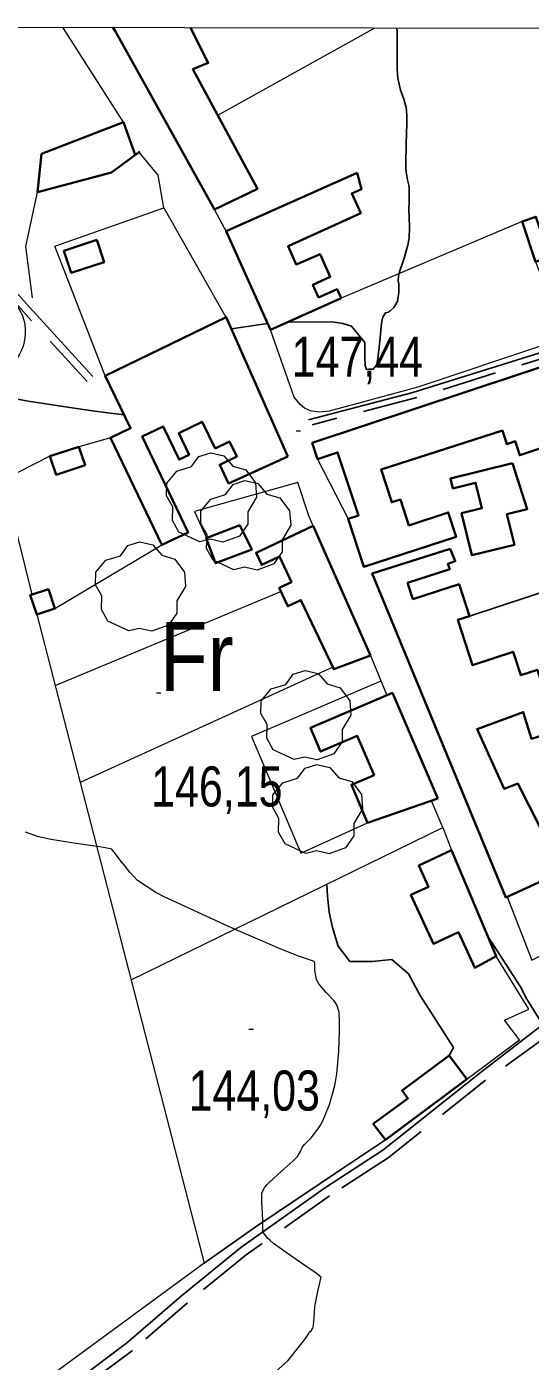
# Model space of a CAD drawing. Extents: x 483855 to 488461, y 4388206 to 4391419.
# Drawn here: x 484185.8 to 484295.6, y 4390781.6 to 4391072.6 of the extents above; entities that cross this region are included whole.
import ezdxf
from ezdxf.enums import TextEntityAlignment as Align

# ---------------------------------------------------------------- set-up
doc = ezdxf.new("R2010")
doc.units = 0
doc.header["$LTSCALE"] = 4
doc.linetypes.add('LONG_DASHED', pattern=[7.5, 6, -1.5])
doc.linetypes.add('MEDIUM_DASHED', pattern=[4.5, 3, -1.5])
for name, color, linetype, lineweight in [('1', 7, 'Continuous', 13), ('25', 7, 'LONG_DASHED', 25), ('29', 7, 'Continuous', 13), ('36', 7, 'Continuous', 25), ('38', 7, 'Continuous', 25), ('47', 7, 'Continuous', 35), ('51', 7, 'Continuous', 13), ('7', 7, 'Continuous', 13), ('8', 7, 'Continuous', 25), ('9', 7, 'Continuous', 13)]:
    doc.layers.add(name, color=color, linetype=linetype, lineweight=lineweight)
doc.layers.add('31', color=7, linetype='Continuous')

msp = doc.modelspace()

# ---------------------------------------------------------------- linework, layer by layer
at = {"layer": '1'}
msp.add_lwpolyline([(484115.5, 4391072.6), (487689.7, 4391065.7), (487685.8, 4388753.5), (484110.5, 4388760.3)], close=True, dxfattribs=at)
at = {"layer": '25'}
msp.add_line((484282.36, 4390944.05), (484413.92, 4390987.45), dxfattribs=at)
for points in [[(484251.23, 4390885.64), (484251.39, 4390883), (484251.77, 4390879.52), (484252.51, 4390876.18), (484253.71, 4390872.09), (484256.25, 4390868.8), (484261.13, 4390868.8), (484265.42, 4390869.2), (484269.07, 4390866.07), (484271.58, 4390861.38), (484278.9, 4390850.03), (484277.96, 4390848.27)], [(484224.54, 4390803), (484235.61, 4390810.89), (484254.44, 4390823.52), (484264.05, 4390829.93)]]:
    msp.add_lwpolyline(points, dxfattribs=at)
at = {"layer": '29'}
for points in [[(484223.56, 4390960.27), (484219.02, 4390962.39), (484217.61, 4390964.93), (484217.71, 4390967.91), (484216.34, 4390970.32), (484216.38, 4390973.07), (484218.54, 4390975.67), (484221.73, 4390976.67), (484223.38, 4390978.86), (484225.95, 4390979.69), (484228.81, 4390979.04), (484230.76, 4390976.77), (484233.57, 4390975.95), (484235.7, 4390973.1), (484235.94, 4390969.97), (484234.06, 4390966.82), (484234.06, 4390964.14), (484232.24, 4390961.53), (484228.62, 4390960.19), (484225.85, 4390960.82)], [(484231, 4390954.18), (484226.46, 4390956.3), (484225.05, 4390958.84), (484225.15, 4390961.82), (484223.78, 4390964.23), (484223.82, 4390966.98), (484225.98, 4390969.58), (484229.17, 4390970.58), (484230.82, 4390972.77), (484233.39, 4390973.6), (484236.25, 4390972.95), (484238.2, 4390970.68), (484241.01, 4390969.86), (484243.14, 4390967.01), (484243.38, 4390963.88), (484241.5, 4390960.73), (484241.5, 4390958.05), (484239.68, 4390955.44), (484236.06, 4390954.1), (484233.29, 4390954.73)], [(484208.08, 4390940.84), (484203.54, 4390942.96), (484202.13, 4390945.5), (484202.23, 4390948.48), (484200.86, 4390950.89), (484200.9, 4390953.64), (484203.06, 4390956.24), (484206.25, 4390957.24), (484207.9, 4390959.43), (484210.47, 4390960.26), (484213.33, 4390959.61), (484215.28, 4390957.34), (484218.09, 4390956.52), (484220.22, 4390953.67), (484220.46, 4390950.54), (484218.58, 4390947.39), (484218.58, 4390944.71), (484216.76, 4390942.1), (484213.14, 4390940.76), (484210.37, 4390941.39)], [(484244.12, 4390912.79), (484239.58, 4390914.91), (484238.17, 4390917.45), (484238.27, 4390920.43), (484236.9, 4390922.84), (484236.94, 4390925.59), (484239.1, 4390928.19), (484242.29, 4390929.19), (484243.94, 4390931.38), (484246.51, 4390932.21), (484249.37, 4390931.56), (484251.32, 4390929.29), (484254.13, 4390928.47), (484256.26, 4390925.62), (484256.5, 4390922.49), (484254.62, 4390919.34), (484254.62, 4390916.66), (484252.8, 4390914.05), (484249.18, 4390912.71), (484246.41, 4390913.34)], [(484246.68, 4390892.33), (484242.14, 4390894.45), (484240.73, 4390896.99), (484240.83, 4390899.97), (484239.46, 4390902.38), (484239.5, 4390905.13), (484241.66, 4390907.73), (484244.85, 4390908.73), (484246.5, 4390910.92), (484249.07, 4390911.75), (484251.93, 4390911.1), (484253.88, 4390908.83), (484256.69, 4390908.01), (484258.82, 4390905.16), (484259.06, 4390902.03), (484257.18, 4390898.88), (484257.18, 4390896.2), (484255.36, 4390893.59), (484251.74, 4390892.25), (484248.97, 4390892.88)]]:
    msp.add_lwpolyline(points, close=True, dxfattribs=at)
at = {"layer": '36'}
msp.add_lwpolyline([(484286.4, 4390874.18), (484293.5, 4390863.28), (484294.88, 4390860.55), (484297.89, 4390855.67), (484301.36, 4390851.1), (484304.67, 4390847.22), (484307.34, 4390843.83)], dxfattribs=at)
at = {"layer": '38'}
for points in [[(484446.6, 4391071.03), (484420.26, 4391057.4), (484410.47, 4391050.18), (484405.1, 4391046.04), (484399.1, 4391040.81), (484389.82, 4391033.18), (484375.53, 4391027.31), (484343.45, 4391017.59), (484326.91, 4391010.64), (484304.24, 4391003.47), (484269.98, 4390992.8), (484247.23, 4390986.88)], [(484200.26, 4390996.32), (484186.42, 4391011.45), (484181.12, 4391017.39), (484178.55, 4391018.61), (484169.32, 4391017.61), (484165.88, 4391015.98), (484162.83, 4391013.24), (484160.39, 4391010.8), (484157.14, 4391007.67), (484151.89, 4391001.63), (484147.35, 4390985.86), (484131.5, 4390937.5), (484130.32, 4390935.61), (484122.52, 4390930.52), (484115.19, 4390927.03)], [(484298.38, 4390855.03), (484284.66, 4390844.48), (484263.45, 4390827.61), (484250.72, 4390819.35), (484232.48, 4390806.42), (484219.57, 4390795.92), (484207.6, 4390785.54), (484197.08, 4390777.65), (484194.16, 4390775.6), (484191.43, 4390772.82), (484188.02, 4390770.33), (484185.14, 4390766.66)]]:
    msp.add_lwpolyline(points, dxfattribs=at)
at = {"layer": '38', "linetype": 'MEDIUM_DASHED'}
for points in [[(484449.68, 4391071.02), (484421.9, 4391056.65), (484412.32, 4391049.58), (484407.04, 4391045.51), (484401.08, 4391040.31), (484391.43, 4391032.38), (484376.62, 4391026.3), (484344.55, 4391016.58), (484328.03, 4391009.64), (484305.23, 4391002.42), (484270.89, 4390991.73), (484248.08, 4390985.8)], [(484199.03, 4390995.19), (484185.18, 4391010.33), (484180.09, 4391016.03), (484178.26, 4391016.89), (484169.78, 4391015.97), (484166.81, 4391014.57), (484163.98, 4391012.03), (484161.56, 4391009.6), (484158.35, 4391006.51), (484153.39, 4391000.81), (484148.95, 4390985.37), (484133.02, 4390936.79), (484131.55, 4390934.41), (484123.34, 4390929.06), (484115.18, 4390925.16)], [(484299.91, 4390853), (484285.88, 4390842.88), (484264.62, 4390825.98), (484251.84, 4390817.69), (484233.7, 4390804.82), (484220.86, 4390794.38), (484208.86, 4390783.98), (484198.26, 4390776.03), (484195.47, 4390774.06), (484192.74, 4390771.29), (484189.43, 4390768.87), (484186.7, 4390765.4), (484184, 4390762.15)]]:
    msp.add_lwpolyline(points, dxfattribs=at)
at = {"layer": '47'}
for p, q in [((484204.64, 4391072.43), (484205.16, 4391071.5)), ((484204.64, 4391072.43), (484205.16, 4391071.5)), ((484222.01, 4391071.46), (484221.54, 4391072.4)), ((484222.01, 4391071.46), (484221.54, 4391072.4)), ((484209.46, 4391044.61), (484206.94, 4391051.73))]:
    msp.add_line(p, q, dxfattribs=at)
for points in [[(484205.16, 4391071.5), (484226.74, 4391032.72), (484236.16, 4391037.23), (484222.04, 4391063.3), (484225.41, 4391064.66), (484222.01, 4391071.46)], [(484206.94, 4391051.73), (484189.03, 4391044.84), (484188.18, 4391036.48), (484204.35, 4391040.78), (484210.46, 4391045.35)]]:
    msp.add_lwpolyline(points, dxfattribs=at)
for points in [[(484257.84, 4391040.72), (484229.35, 4391028), (484238.95, 4391006.48), (484254.38, 4391013.38), (484253.49, 4391015.35), (484249.46, 4391013.55), (484248.21, 4391016.32), (484252.02, 4391018.04), (484249.77, 4391023.01), (484244.61, 4391020.69), (484242.8, 4391024.69), (484258.67, 4391031.88), (484256.7, 4391036.21), (484258.82, 4391037.18)], [(484313.87, 4391034.52), (484317.24, 4391024.43), (484301.67, 4391019.25), (484300.57, 4391022.55), (484296.75, 4391021.29), (484293.83, 4391030.11), (484296.85, 4391031.12), (484298.18, 4391027.11), (484305.85, 4391029.67), (484304.96, 4391032.32)], [(484201.1, 4391026.07), (484193.94, 4391023.7), (484195.54, 4391018.87), (484202.7, 4391021.24)], [(484242.75, 4390978.86), (484229.32, 4391009.26), (484202.93, 4390996.48), (484208.47, 4390985.02), (484204.11, 4390982.93), (484215.3, 4390959.58), (484221.01, 4390962.31), (484211.01, 4390983.21), (484215.58, 4390985.41), (484219.05, 4390978.18), (484221.23, 4390979.23), (484218.96, 4390983.92), (484224.09, 4390986.41), (484226.89, 4390980.63), (484230.03, 4390982.15), (484231.62, 4390978.84), (484227.92, 4390977.08), (484229.85, 4390973)], [(484304.25, 4391000.42), (484248.07, 4390981.84), (484249.24, 4390978.3), (484253.59, 4390979.76), (484258.19, 4390966.02), (484255.93, 4390965.28), (484259.35, 4390954.81), (484279.44, 4390961.38), (484277.71, 4390966.66), (484269.15, 4390963.85), (484267.29, 4390969.49), (484265.4, 4390968.89), (484263.11, 4390976.06), (484289.54, 4390984.51), (484290.47, 4390981.57), (484292.32, 4390982.18), (484293.31, 4390979.15), (484299.89, 4390981.33), (484298.31, 4390986.08), (484297.95, 4390985.96), (484298.09, 4390985.52), (484308.65, 4390988.4)], [(484197.22, 4390981), (484190.9, 4390978.91), (484192.23, 4390974.89), (484198.55, 4390976.98)], [(484291.75, 4390977.43), (484278.21, 4390974.06), (484278.73, 4390971.92), (484283.7, 4390973.16), (484285.08, 4390967.59), (484280.64, 4390966.49), (484282.9, 4390957.35), (484292.15, 4390959.63), (484290.5, 4390966.28), (484294.94, 4390967.4)], [(484232.26, 4390963.86), (484224.92, 4390961.09), (484226.99, 4390955.59), (484234.88, 4390958.58)], [(484260.76, 4390935.51), (484248.26, 4390963.74), (484235.82, 4390957.87), (484237.06, 4390955.23), (484240.92, 4390957.04), (484243.53, 4390951.47), (484240.87, 4390950.22), (484242.75, 4390946.21), (484245.62, 4390947.57), (484252.75, 4390932.5)], [(484278.12, 4390958.71), (484261.12, 4390953.34), (484290.31, 4390882.75), (484302.64, 4390888.43), (484292.92, 4390907.57), (484289.89, 4390906.45), (484284.03, 4390919.43), (484294.08, 4390923.13), (484295.91, 4390917.32), (484301.4, 4390919.07), (484297.16, 4390932.34), (484293.55, 4390931.18), (484291.91, 4390936.27), (484282.99, 4390933.41), (484279.84, 4390943.23), (484282.36, 4390944.05), (484280.08, 4390951.03), (484270.04, 4390947.77), (484268.88, 4390951.31), (484278.06, 4390954.32), (484277.67, 4390955.5), (484279.24, 4390956.03)], [(484190.58, 4390949.97), (484186.62, 4390948.66), (484188.02, 4390944.41), (484191.98, 4390945.72)], [(484275.43, 4390904.29), (484265.54, 4390927.33), (484247.68, 4390919.68), (484249.88, 4390914.53), (484257.88, 4390917.97), (484261.56, 4390909.4), (484256.63, 4390907.29), (484260.16, 4390899.04)], [(484288.18, 4390869.95), (484278.4, 4390893.02), (484271.28, 4390889.68), (484273.4, 4390885.07), (484269.6, 4390883.33), (484274.49, 4390872.63), (484279.96, 4390875.14), (484283.5, 4390867.41)], [(484264.05, 4390829.93), (484281.81, 4390843.11), (484277.96, 4390848.27), (484267.68, 4390840.62), (484268.92, 4390838.94), (484261.37, 4390833.37)]]:
    msp.add_lwpolyline(points, close=True, dxfattribs=at)
at = {"layer": '51'}
for p, q in [((484194.29, 4391071.52), (484193.7, 4391072.45)), ((484194.29, 4391071.52), (484193.7, 4391072.45)), ((484206.94, 4391051.73), (484194.29, 4391071.52)), ((484227.5, 4391053.25), (484260.04, 4391071.39)), ((484260.04, 4391071.39), (484261.7, 4391072.32)), ((484260.04, 4391071.39), (484261.7, 4391072.32)), ((484229.55, 4391027.57), (484226.74, 4391032.72)), ((484293.83, 4391030.11), (484254.38, 4391013.38)), ((484204.11, 4390982.93), (484197.22, 4390981)), ((484249.24, 4390978.3), (484255.93, 4390965.28)), ((484191.98, 4390945.72), (484215.3, 4390959.58)), ((484192.03, 4390928.91), (484241.25, 4390949.42)), ((484188.02, 4390944.41), (484224.54, 4390803)), ((484260.76, 4390935.51), (484264.28, 4390926.98)), ((484252.56, 4390932.91), (484197.48, 4390907.79)), ((484276.54, 4390898), (484274.1, 4390903.83))]:
    msp.add_line(p, q, dxfattribs=at)
for points in [[(484215.7, 4391033.1), (484214.48, 4391040.18), (484210.26, 4391045.29)], [(484187.06, 4391013.49), (484185.62, 4391024.67), (484188.18, 4391036.48)], [(484202.93, 4390996.48), (484191.94, 4391024.74), (484215.7, 4391033.1), (484229.23, 4391009.22)], [(484296.75, 4391021.29), (484302.37, 4391007.06), (484301.58, 4391005.27), (484298.9, 4391003.3), (484271.13, 4390993.99), (484251.8, 4390988.78), (484249.51, 4390988.55), (484247.7, 4390988.81), (484246.42, 4390989.38), (484245.41, 4390990.21), (484244.17, 4390991.82), (484238.95, 4391006.48)], [(484190.9, 4390978.91), (484180.8, 4390973.79), (484186.98, 4390948.78)], [(484248.67, 4390962.89), (484247.37, 4390965.92), (484244.93, 4390973.18), (484222.42, 4390966.85), (484225.04, 4390961.14)], [(484290.59, 4390882.88), (484295.95, 4390869.05), (484364.32, 4390904.65), (484440.04, 4390940.66)], [(484263.06, 4390929.92), (484234.84, 4390917.82), (484245.61, 4390892.4), (484260.16, 4390899.04)], [(484208.58, 4390864.81), (484276.54, 4390898), (484278.4, 4390893.02)], [(484281.81, 4390843.11), (484293.29, 4390851.72), (484289.96, 4390856), (484295.28, 4390858.41), (484288.18, 4390869.95)], [(484224.54, 4390803), (484180.2, 4390770.44), (484149.86, 4390698.23), (484127.82, 4390646.12), (484114.51, 4390615.64)]]:
    msp.add_lwpolyline(points, dxfattribs=at)
msp.add_ellipse((484175.55, 4391006.01), major_axis=(6.13, -7.87), ratio=0.999508, dxfattribs=at)
at = {"layer": '7'}
for p, q in [((484244.55, 4390984.49), (484245.55, 4390984.49)), ((484214.1, 4390927.34), (484215.1, 4390927.34)), ((484234.27, 4390854.05), (484235.27, 4390854.05))]:
    msp.add_line(p, q, dxfattribs=at)
at = {"layer": '8'}
for p, q in [((484266.55, 4391072.31), (484266.6, 4391071.38)), ((484238.34, 4391007.85), (484230.46, 4391006.68))]:
    msp.add_line(p, q, dxfattribs=at)
for points in [[(484266.6, 4391071.38), (484266.6, 4391068.05), (484266.58, 4391063.36), (484266.64, 4391062.3), (484266.73, 4391061.35), (484267.29, 4391058.75), (484267.95, 4391057.01), (484268.09, 4391056.59), (484268.22, 4391056.2)], [(484268.22, 4391056.2), (484268.55, 4391055.03), (484268.7, 4391053.2), (484268.71, 4391052.4), (484268.7, 4391051.47), (484268.58, 4391047.04), (484268.49, 4391042.63), (484268.51, 4391041.71), (484268.55, 4391040.93), (484268.83, 4391039.19), (484269.14, 4391037.99), (484269.19, 4391037.53), (484269.22, 4391037.03), (484269.22, 4391034.79), (484269.17, 4391032.31), (484269.18, 4391031.65), (484269.19, 4391031.01), (484269.3, 4391028.8), (484269.21, 4391026.45), (484269.09, 4391025.72), (484268.93, 4391024.95), (484268.02, 4391021.87), (484267.12, 4391019.12), (484266.96, 4391018.56), (484266.85, 4391018.09), (484266.79, 4391017.13), (484266.94, 4391016.5), (484266.97, 4391016.25), (484266.99, 4391015.96), (484266.98, 4391014.62), (484266.77, 4391013.17), (484266.66, 4391012.81), (484266.52, 4391012.47), (484265.85, 4391011.38), (484265.08, 4391010.6), (484264.88, 4391010.46), (484264.68, 4391010.34), (484264.03, 4391010.18), (484263.48, 4391009.25), (484263.34, 4391008.66), (484263.21, 4391007.92), (484262.81, 4391004.03), (484262.37, 4391000.13), (484262.22, 4390999.4), (484262.06, 4390998.8), (484261.38, 4390997.88), (484260.7, 4390997.9), (484260.54, 4390997.89), (484260.38, 4390997.88), (484259.92, 4390997.82), (484259.63, 4390998.68), (484259.59, 4390999.25), (484259.56, 4390999.96), (484259.57, 4391003.75), (484256.65, 4391007.29), (484254.77, 4391007.86), (484252.43, 4391008.24), (484242.66, 4391008.14)], [(484207.05, 4390987.95), (484202.91, 4390988.43), (484200.71, 4390988.73), (484198.17, 4390989.1), (484186.18, 4390990.93), (484174.07, 4390993.18)]]:
    msp.add_lwpolyline(points, dxfattribs=at)
at = {"layer": '9'}
for points in [[(484248.52, 4390868.74), (484248.17, 4390868.92), (484245.09, 4390869.93), (484243.3, 4390870.65), (484241.11, 4390871.56), (484229.83, 4390876.42), (484218.31, 4390881.68), (484215.97, 4390882.83), (484214, 4390883.85), (484209.95, 4390886.46), (484208.38, 4390888.2), (484207.97, 4390888.68), (484207.58, 4390889.16), (484206.24, 4390890.86), (484205.19, 4390892.25), (484204.97, 4390892.54), (484204.78, 4390892.77), (484204.36, 4390893.25), (484202.97, 4390893.57), (484202.17, 4390893.7), (484201.18, 4390893.85), (484196.13, 4390894.56), (484190.71, 4390895.44), (484189.5, 4390895.7), (484188.42, 4390895.97), (484185.55, 4390896.98)], [(484238.87, 4390778.29), (484242.73, 4390781.75), (484245.61, 4390785.3), (484246.16, 4390786.01), (484246.6, 4390786.59), (484247.31, 4390787.68), (484247.4, 4390787.95), (484247.46, 4390788.01), (484247.52, 4390788.07), (484247.86, 4390788.26), (484248.21, 4390788.81), (484248.28, 4390789.1), (484248.34, 4390789.45), (484248.49, 4390791.22), (484248.67, 4390793.4), (484248.75, 4390794.01), (484248.84, 4390794.63), (484249.3, 4390796.86), (484249.74, 4390798.7), (484249.82, 4390799.06), (484249.89, 4390799.37), (484250.01, 4390799.95), (484249.04, 4390800.75), (484248.42, 4390801.19), (484247.66, 4390801.73), (484243.65, 4390804.45), (484239.66, 4390807.32), (484238.9, 4390807.94), (484238.29, 4390808.49), (484237.34, 4390809.84), (484237.34, 4390811.02), (484237.33, 4390811.45), (484237.31, 4390811.94), (484237.21, 4390814.07), (484237.11, 4390816.21), (484237.09, 4390816.7), (484237.08, 4390817.14), (484237.08, 4390818.34), (484237.75, 4390819.6), (484238.16, 4390820.08), (484238.67, 4390820.61), (484241.31, 4390822.99), (484243.94, 4390825.32), (484244.45, 4390825.82), (484244.86, 4390826.26), (484245.52, 4390827.32), (484245.89, 4390828.19), (484246.11, 4390828.5), (484246.39, 4390828.85), (484247.83, 4390830.35), (484249.53, 4390832.49), (484249.98, 4390833.24), (484250.41, 4390834.06), (484251.86, 4390837.58), (484253.01, 4390841.77), (484253.24, 4390843.01), (484253.44, 4390844.28), (484253.88, 4390849.18), (484254.01, 4390853.61), (484254.02, 4390854.59), (484254.02, 4390855.46), (484253.93, 4390857.7), (484253.41, 4390859.3), (484253.13, 4390859.77), (484252.8, 4390860.24), (484251.14, 4390862.04), (484249.52, 4390863.91), (484249.22, 4390864.42), (484248.98, 4390864.94), (484248.64, 4390866.82), (484248.62, 4390868.28), (484248.58, 4390868.54), (484248.52, 4390868.74)]]:
    msp.add_lwpolyline(points, dxfattribs=at)

# ---------------------------------------------------------------- texts
at = {"layer": '31', "width": 0.85}
msp.add_text('Fr', height=15, dxfattribs=at).set_placement((484222.9, 4390927.78), align=Align.CENTER)
at = {"layer": '7', "width": 0.8}
for s, p in [('147,44', (484243.6, 4390996.24)), ('146,15', (484212.96, 4390902.56)), ('144,03', (484221.13, 4390836.27))]:
    msp.add_text(s, height=8.75, dxfattribs=at).set_placement(p)

doc.saveas('drawing.dxf')
